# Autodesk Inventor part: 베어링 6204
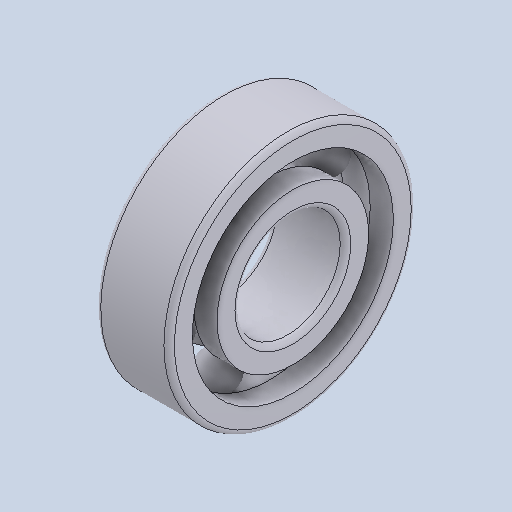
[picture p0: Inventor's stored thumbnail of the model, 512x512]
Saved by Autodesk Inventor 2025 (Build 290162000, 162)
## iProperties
Created: 2025-08
Part Number: 베어링 6204
Material: 강철, 연강
Description: 깊은 그루브 볼 베어링
Document SubType Name: Modeling
Designer: infra04
Density: 7.86 g/cm^3
Appearance: 기본값
Author: jhkim
Sending System: Autodesk Inventor 2026
Preprocessor: ST-DEVELOPER v20.1
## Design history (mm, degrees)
feature "Solid1"
feature "Solid1:1"
feature "Solid1:2"
feature "Solid1:3"
feature "Solid1:4"
feature "Solid1:5"
feature "Solid1:6"
feature "Solid1:7"
feature "Solid1:8"
node "솔리드1"
node "솔리드2"
node "솔리드3"
node "솔리드4"
node "솔리드5"
node "솔리드6"
node "솔리드7"
node "솔리드8"
node "솔리드9"
